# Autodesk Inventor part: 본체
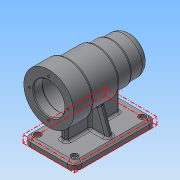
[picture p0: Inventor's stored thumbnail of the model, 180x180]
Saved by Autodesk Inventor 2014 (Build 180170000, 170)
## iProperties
Created: 2016-06
Part Number: 본체
Material: 일반
Document SubType Name: Modeling
Designer: NET
Density: 1 g/cm^3
Appearance: 기본값
Author: NET
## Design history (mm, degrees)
sketch "스케치1"
  geometry: C1 r 25 at (0, 0); 1 further point
  constraints: 1 centre point, 1 coincident
  dimensions: "d1" = 50 diameter of C1
extrude "돌출1" new body sketch "스케치1" stored distance "d2" = 25; taper "d3" = 0 deg
sketch "스케치2"
  geometry: C1 r 25 at (0, 0) reference; C2 r 27 at (0, 0)
  constraints: 1 centre point, 1 coincident
  dimensions: "d4" = 54 diameter of C2
extrude "돌출2" join sketch "스케치2" distance "d5" = 20; taper "d6" = 0 deg
sketch "스케치3"
  geometry: C1 r 27 at (0, 0) reference; C2 r 30 at (0, 0)
  constraints: 1 centre point, 1 coincident
  dimensions: "d7" = 60 diameter of C2
extrude "돌출3" join sketch "스케치3" distance "d8" = 39; taper "d9" = 0 deg
sketch "스케치4"
  geometry: C1 r 30 at (0, 0) reference; C2 r 34 at (0, 0)
  constraints: 1 centre point, 1 coincident
  dimensions: "d10" = 68 diameter of C2
extrude "돌출4" join sketch "스케치4" distance "d11" = 28; taper "d12" = 0 deg
sketch "스케치6"
  geometry: L1 (12.5, -25)-(12.5, 25) reference; L2 (-99.5, 34)-(-99.5, -34) reference; L3 (-99.5, 0)-(12.5, 0); L4 (-99.5, 21)-(-87.5, 21); L5 (-87.5, 21)-(-87.5, 0); L6 (-87.5, 0)-(-87.5, 21); L7 (-84.5, 24)-(-36.5, 24); L8 (-33.5, 21)-(-33.5, 0); L9 (-33.5, 21)-(-21.8, 21); L10 (-21.5, 20.7)-(-21.5, 0); L11 (-21.5, 17.5)-(-3.8, 17.5); L12 (-3.5, 17.2)-(-3.5, 0); L13 (0.5, 0)-(0.5, 15.7); L14 (0.2, 16)-(-3.5, 16); L15 (3.5, 0)-(3.5, 7.5); L16 (0.5, 10.5)-(0.5, 10.5); A1 r 3 centre (0.5, 7.5) between (3.5, 7.5) and (0.5, 10.5); A2 r 0.3 centre (0.2, 15.7) between (0.5, 15.7) and (0.2, 16); A3 r 0.3 centre (-3.8, 17.2) between (-3.5, 17.2) and (-3.8, 17.5); A4 r 0.3 centre (-21.8, 20.7) between (-21.5, 20.7) and (-21.8, 21); A5 r 3 centre (-36.5, 21) between (-33.5, 21) and (-36.5, 24); A6 r 3 centre (-84.5, 21) between (-84.5, 24) and (-87.5, 21); 1 further point
  constraints: 28 end point, 12 point on circle, 12 tangent, 11 perpendicular, 11 point on line, 6 centre point, 3 equal radius, 2 midpoint, 1 collinear, 1 parallel
  dimensions: "d13" = 42 diameter of L4 L3; "d15" = 32 diameter of L14 L3; "d16" = 35 diameter of L11 L3; "d17" = 42 diameter of L9 L3; "d18" = 48 diameter of L7 L3; "d24" = 12 distance between parallel lines of L2 L5; "d25" = 54 distance between parallel lines of L8 L5; "d26" = 12 distance between parallel lines of L10 L8; "d27" = 18 distance between parallel lines of L12 L10; "d29" = 4 distance between parallel lines of L12 L13; "d30" = 3 distance between parallel lines of L13 L15; "d31" = 21 diameter of L16 L3; "d32" = 3 radius of A1; "d33" = 0.3 radius of A2; "d34" = 3 radius of A5
revolve "회전1" sketch "스케치6" stored, may be unused: angle "d35" = 90 deg
chamfer "모따기1" distance "d36" = 1; stored, may be unused: second distance "d37" = 2, angle "d38" = 45 deg
sketch "스케치7" dims "d39" = 52
  geometry: L1 (0, 0)-(0, 26); C1 r 22 at (0, 0) reference
  constraints: 2 end point, 1 coincident, 1 vertical, 1 vertical alignment, 2 other
hole "구멍1" sketch "스케치7" at (0, 26) diameter "d40" = 3.242; stored, may be unused: countersink angle "d44" = 90 deg, drill point angle "d46" = 118 deg; dims "d41" = 8, "d42" = 4, "d43" = 2, "d45" = 11
fillet "모깎기1" dims "d50" = 10
fillet "모깎기2" dims "d51" = 3
node "작업 평면1"
sketch "스케치8"
  geometry: L1 (-35, -99.5)-(35, -99.5); L2 (35, -99.5)-(35, 12.5); L3 (35, 12.5)-(-35, 12.5); L4 (-35, 12.5)-(-35, -99.5); L5 (-34, -99.5)-(34, -99.5) reference; L6 (-15, 12.5)-(15, 12.5) reference; L7 (0, -99.5)-(0, 12.5); 4 further points
  constraints: 10 end point, 5 midpoint, 2 parallel, 1 horizontal, 1 horizontal alignment, 1 perpendicular, 1 vertical alignment
  dimensions: "d53" = 112 distance of L3.end L1.start; "d54" = 70 distance of L1.start L1.end
extrude "돌출5" join sketch "스케치8" distance "d55" = 10; taper "d56" = 0 deg
fillet "모깎기10" dims "d89" = 10
chamfer "모따기2" distance "d57" = 4; stored, may be unused: second distance "d58" = 2, angle "d59" = 45 deg
sketch "스케치11"
  geometry: L1 (-4, -79.5)-(4, -79.5); L2 (4, -79.5)-(4, -7.5); L3 (4, -7.5)-(-4, -7.5); L4 (-4, -7.5)-(-4, -79.5); L5 (25, 12.5)-(-25, 12.5) reference; L6 (-25, -99.5)-(25, -99.5) reference; 6 further points
  constraints: 8 end point, 2 parallel, 1 horizontal, 1 midpoint, 1 perpendicular, 1 vertical alignment
  dimensions: "d63" = 8 distance between parallel lines of L2 L4; "d64" = 20 distance between parallel lines of L5 L3; "d65" = 20 distance between parallel lines of L6 L1
extrude "돌출6" join sketch "스케치11" stored distance "d66" = 10; taper "d67" = 0 deg
node "작업 평면2"
sketch "스케치16"
  geometry: L1 (-25, -60)-(25, -60) reference; L2 (-31, -60)-(-25, -60) reference; L3 (25, -60)-(31, -60) reference; L4 (-15.306, -25.122)-(-28, -60); L5 (-15.306, -25.122)-(15.306, -25.122); L6 (-35, -70)-(-35, -64) reference; L7 (15.306, -25.122)-(28, -60); L8 (35, -64)-(35, -70) reference; L9 (-28, -60)-(28, -60); A1 r 30 centre (0, 0) between (4, -29.732) and (-4, -29.732) reference; 1 further point
  constraints: 8 end point, 2 point on line, 1 parallel, 1 perpendicular
  dimensions: "d90" = 7 distance from line of L6 L4.end; "d91" = 7 distance from line of L8 L7.end; "d92" = 110 deg angle of L2 L4; "d93" = 110 deg angle of L3 L7; "d94" = 30.611 distance of L4.start L5.end
extrude "돌출8" join sketch "스케치16" stored distance "d95" = 8; taper "d96" = 0 deg
fillet "모깎기11" dims "d97" = 3
fillet "모깎기12" dims "d98" = 3
fillet "모깎기13" dims "d99" = 3
fillet "모깎기14" dims "d100" = 3
fillet "모깎기15" dims "d101" = 3
sketch "스케치18"
  geometry: C1 r 4.5 at (-25, -89.5); C2 r 4.5 at (25, -89.5); C3 r 4.5 at (25, 2.5); C4 r 4.5 at (-25, 2.5); A1 r 6 centre (25, 2.5) between (31, 2.5) and (25, 8.5) reference; A2 r 6 centre (-25, 2.5) between (-25, 8.5) and (-31, 2.5) reference; A3 r 6 centre (-25, -89.5) between (-31, -89.5) and (-25, -95.5) reference; A4 r 6 centre (25, -89.5) between (25, -95.5) and (31, -89.5) reference; 1 further point
  constraints: 4 centre point, 4 coincident
  dimensions: "d102" = 9 diameter of C1; "d103" = 9 diameter of C2; "d104" = 9 diameter of C3; "d105" = 9 diameter of C4
extrude "돌출9" cut sketch "스케치18" distance "d106" = 4; taper "d107" = 0 deg
sketch "스케치19"
  geometry: C1 r 4.5 at (0, 0) reference; C2 r 4.5 at (-50, 0) reference; C3 r 4.5 at (-50, 92) reference; C4 r 4.5 at (0, 92) reference; C5 r 4.5 at (0, 92) reference; C6 r 2.5 at (-50, 0); C7 r 2.5 at (0, 0); C8 r 2.5 at (0, 92); C9 r 2.5 at (-50, 92); 1 further point
  constraints: 4 centre point, 4 coincident
  dimensions: "d108" = 5 diameter of C6; "d109" = 5 diameter of C7; "d110" = 5 diameter of C8; "d111" = 5 diameter of C9
extrude "돌출10" cut sketch "스케치19" stored distance "d112" = 4; taper "d113" = 0 deg
node "작업 평면4"
sketch "스케치21"
  geometry: L1 (99.5, -34)-(99.5, 34) reference; 2 further points
  constraints: 1 horizontal alignment, 1 other
  dimensions: "d116" = 48 distance from line of L1 point (51.5, 0)
feature "엠보싱1" sketch "스케치21" dims "d2" = 25, "d117" = 0.5, "d118" = 0
node "솔리드1"
pattern_circular "원형 패턴1" dims angle "d48" = 360 deg
node "투영된 루프1"
node "투영된 루프2"
